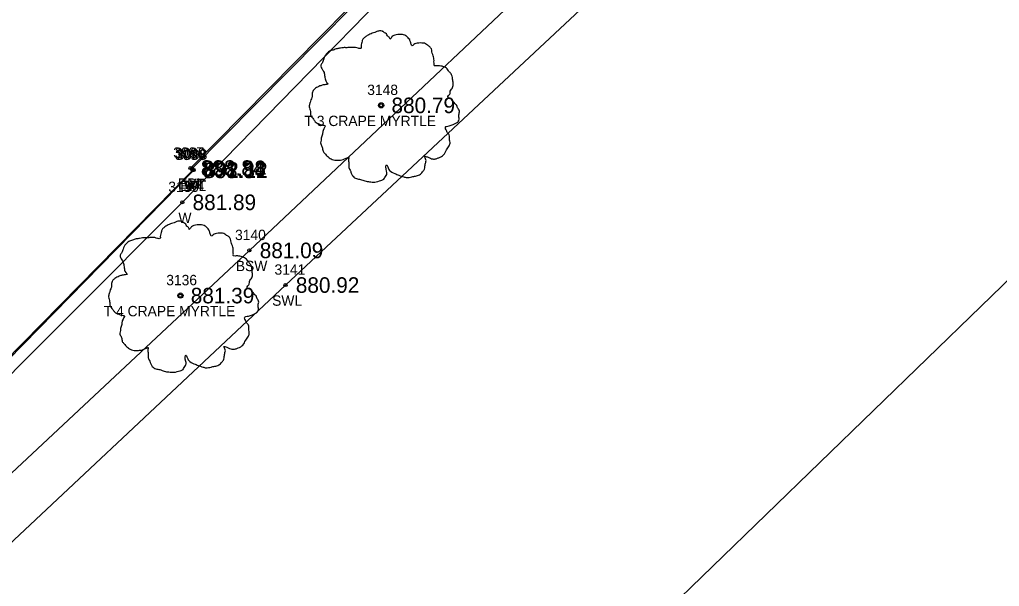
# Model space of a CAD drawing. Extents: x 1622501 to 1626664, y 1117816 to 1121579.
# Drawn here: x 1623634 to 1623728.6, y 1119016.9 to 1119071.7 of the extents above; entities that cross this region are included whole.
import ezdxf

# ---------------------------------------------------------------- set-up
doc = ezdxf.new("R2010")
doc.units = 0
for name, color, linetype in [('RD_EX_BldgApp', 7, 'Continuous'), ('RD_EX_Conc', 7, 'Continuous'), ('RD_EX_Conc_txCode', 7, 'Continuous'), ('RD_EX_Misc', 7, 'Continuous'), ('RD_EX_Misc_txCode', 7, 'Continuous'), ('RD_EX_Road', 7, 'Continuous'), ('RD_EX_Road_txCode', 7, 'Continuous'), ('RD_EX_TX_Conc_ELEV', 7, 'Continuous'), ('RD_EX_TX_Misc_ELEV', 7, 'Continuous'), ('RD_EX_TX_Road_ELEV', 7, 'Continuous'), ('RD_EX_TX_VEG_ELEV', 7, 'Continuous'), ('RD_EX_VEG', 7, 'Continuous'), ('RD_EX_VEG_txCode', 7, 'Continuous'), ('RD_SMD_Locator', 7, 'Continuous')]:
    doc.layers.add(name, color=color, linetype=linetype)

msp = doc.modelspace()

# ---------------------------------------------------------------- linework, layer by layer
at = {"layer": 'RD_EX_BldgApp'}
msp.add_lwpolyline([(1623611.88, 1119041.633), (1623617.165, 1119021.483), (1623649.671, 1119054.028), (1623681.051, 1119086.161), (1623722.347, 1119127.806), (1623757.936, 1119164.001), (1623796.61, 1119203.222), (1623812.892, 1119220.059), (1623805.759, 1119227.093), (1623820.901, 1119266.212)], dxfattribs=at)
at = {"layer": 'RD_EX_Conc'}
for points in [[(1623595.957, 1118993.098), (1623622.153, 1119017.611), (1623656.161, 1119049.385), (1623694.844, 1119085.827), (1623730.881, 1119119.331), (1623767.199, 1119153.546), (1623807.434, 1119191.229), (1623857.127, 1119237.776)], [(1623598.762, 1118988.762), (1623625.502, 1119014.047), (1623659.646, 1119046.042), (1623697.948, 1119081.826), (1623734.479, 1119116.219), (1623770.397, 1119149.723), (1623810.513, 1119187.319), (1623859.029, 1119232.94)]]:
    msp.add_lwpolyline(points, dxfattribs=at)
at = {"layer": 'RD_EX_Misc'}
msp.add_lwpolyline([(1623612.489, 1119041.839), (1623617.784, 1119023.464), (1623650.786, 1119057.144), (1623650.629, 1119057.303), (1623678.345, 1119085.339), (1623703.433, 1119110.78), (1623703.191, 1119111.004), (1623719.28, 1119127.327), (1623719.051, 1119127.54), (1623738.853, 1119148.212), (1623776.594, 1119185.952), (1623789.621, 1119199.191), (1623809.925, 1119220.218), (1623803.282, 1119226.617), (1623818.739, 1119266.256)], dxfattribs=at)
at = {"layer": 'RD_EX_Road'}
for points in [[(1623613.186, 1119042.019), (1623617.82, 1119023.739), (1623650.67, 1119057.113), (1623650.468, 1119057.338), (1623678.183, 1119085.433), (1623703.282, 1119110.828), (1623703.118, 1119110.99), (1623719.085, 1119127.283), (1623718.708, 1119127.648), (1623738.45, 1119148.271), (1623776.492, 1119186.305), (1623774.181, 1119207.708)], [(1623613.186, 1119042.019), (1623611.006, 1119043.814), (1623608.999, 1119042.947), (1623599.734, 1119032.628), (1623594.943, 1119023.41), (1623593.061, 1119016.814), (1623592.292, 1119005.793), (1623594.792, 1118992.799), (1623599.513, 1118985.89), (1623605.793, 1118978.903), (1623613.538, 1118973.355), (1623625.909, 1118968.984), (1623636.836, 1118968.46), (1623647.743, 1118971.195), (1623659.463, 1118979.46), (1623658.889, 1118980.17), (1623658.337, 1118980.438), (1623666.316, 1118985.506), (1623695.703, 1119013.851), (1623731.996, 1119048.998), (1623767.021, 1119082.64), (1623805.037, 1119118.246), (1623840.273, 1119151.616), (1623856.194, 1119167.062)]]:
    msp.add_lwpolyline(points, dxfattribs=at)
at = {"layer": 'RD_EX_VEG'}
for centre, radius in [((1623668.89, 1119063.392), 0.25), ((1623668.877, 1119063.373), 0.0001), ((1623649.496, 1119045.025), 0.25), ((1623649.484, 1119045.006), 0.0001)]:
    msp.add_circle(centre, radius, dxfattribs=at)
for points in [[(1623669.022, 1119070.559), (1623668.722, 1119070.584), (1623668.397, 1119070.484), (1623668.147, 1119070.385), (1623667.922, 1119070.31), (1623667.698, 1119070.21), (1623667.398, 1119070.035), (1623667.173, 1119069.835), (1623667.048, 1119069.585), (1623666.998, 1119069.36), (1623666.948, 1119069.085), (1623666.948, 1119068.91), (1623666.823, 1119068.885), (1623666.673, 1119068.91), (1623666.423, 1119068.985), (1623666.173, 1119068.985), (1623665.923, 1119068.985), (1623665.573, 1119068.96), (1623665.224, 1119068.96), (1623664.949, 1119068.91), (1623664.624, 1119068.86), (1623664.249, 1119068.735), (1623663.899, 1119068.61), (1623663.599, 1119068.36), (1623663.349, 1119067.886), (1623663.224, 1119067.536), (1623663.075, 1119067.286), (1623663.224, 1119066.836), (1623663.399, 1119066.486), (1623663.424, 1119066.286), (1623663.499, 1119065.862), (1623663.599, 1119065.637), (1623663.724, 1119065.437), (1623663.649, 1119065.412), (1623663.274, 1119065.362), (1623662.975, 1119065.262), (1623662.55, 1119065.037), (1623662.325, 1119064.812), (1623662.225, 1119064.487), (1623662.2, 1119064.137), (1623662.1, 1119063.937), (1623662.025, 1119063.662), (1623662, 1119063.587), (1623661.95, 1119063.263), (1623662.05, 1119062.813), (1623662.075, 1119062.463), (1623662.2, 1119062.238), (1623662.35, 1119062.063), (1623662.525, 1119061.813), (1623662.925, 1119061.588), (1623663.249, 1119061.488), (1623663.449, 1119061.463), (1623663.274, 1119060.964), (1623663.224, 1119060.614), (1623663.1, 1119060.214), (1623663.1, 1119060.139), (1623663.05, 1119059.664), (1623663.199, 1119059.339), (1623663.274, 1119058.965), (1623663.449, 1119058.74), (1623663.724, 1119058.44), (1623664.049, 1119058.215), (1623664.549, 1119058.09), (1623664.949, 1119058.115), (1623665.524, 1119058.29), (1623665.773, 1119058.365), (1623665.748, 1119058.19), (1623665.773, 1119057.815), (1623665.773, 1119057.39), (1623665.923, 1119057.065), (1623666.023, 1119056.79), (1623666.173, 1119056.541), (1623666.498, 1119056.316), (1623666.898, 1119056.241), (1623667.323, 1119056.091), (1623667.773, 1119056.016), (1623668.272, 1119055.991), (1623668.872, 1119056.141), (1623669.147, 1119056.266), (1623669.247, 1119056.441), (1623669.447, 1119056.815), (1623669.397, 1119057.04), (1623669.422, 1119057.64), (1623669.522, 1119057.465), (1623669.697, 1119057.115), (1623670.196, 1119056.815), (1623670.596, 1119056.641), (1623671.071, 1119056.491), (1623671.371, 1119056.416), (1623671.846, 1119056.491), (1623672.221, 1119056.566), (1623672.595, 1119056.691), (1623672.895, 1119056.965), (1623673.07, 1119057.24), (1623673.12, 1119057.515), (1623673.195, 1119057.89), (1623673.245, 1119058.065)], [(1623673.245, 1119058.065), (1623673.17, 1119058.24), (1623673.12, 1119058.49), (1623673.195, 1119058.465), (1623673.37, 1119058.415), (1623673.645, 1119058.29), (1623673.87, 1119058.215), (1623674.195, 1119058.24), (1623674.47, 1119058.34), (1623674.919, 1119058.615), (1623675.194, 1119059.089), (1623675.469, 1119059.489), (1623675.544, 1119059.814), (1623675.494, 1119060.039), (1623675.469, 1119060.539), (1623675.269, 1119060.789), (1623675.219, 1119060.914), (1623675.119, 1119061.313), (1623675.194, 1119061.363), (1623675.469, 1119061.413), (1623675.844, 1119061.538), (1623676.119, 1119061.663), (1623676.344, 1119061.838), (1623676.419, 1119062.063), (1623676.394, 1119062.463), (1623676.444, 1119062.863), (1623676.369, 1119063.013), (1623676.269, 1119063.163), (1623676.194, 1119063.363), (1623676.044, 1119063.512), (1623675.944, 1119063.662), (1623675.844, 1119063.762), (1623675.719, 1119063.912), (1623675.544, 1119064.037), (1623675.394, 1119064.087), (1623675.344, 1119064.237), (1623675.494, 1119064.437), (1623675.544, 1119064.537), (1623675.569, 1119064.762), (1623675.794, 1119065.112), (1623675.844, 1119065.512), (1623675.794, 1119065.936), (1623675.744, 1119066.211), (1623675.594, 1119066.486), (1623675.394, 1119066.736), (1623675.269, 1119066.911), (1623675.094, 1119067.036), (1623674.769, 1119067.161), (1623674.52, 1119067.211), (1623674.17, 1119067.211), (1623673.97, 1119067.261), (1623673.995, 1119067.311), (1623673.995, 1119067.461), (1623673.995, 1119067.736), (1623673.92, 1119068.185), (1623673.77, 1119068.685), (1623673.77, 1119068.71), (1623673.67, 1119068.96), (1623673.445, 1119069.16), (1623673.27, 1119069.26), (1623673.07, 1119069.385), (1623672.82, 1119069.41), (1623672.52, 1119069.41), (1623672.246, 1119069.36), (1623672.046, 1119069.26), (1623671.871, 1119069.135), (1623671.796, 1119069.285), (1623671.696, 1119069.585), (1623671.646, 1119069.735), (1623671.496, 1119069.91), (1623671.271, 1119070.11), (1623670.821, 1119070.235), (1623670.196, 1119070.16), (1623669.897, 1119069.96), (1623669.747, 1119069.785), (1623669.697, 1119069.91), (1623669.497, 1119070.11), (1623669.397, 1119070.285), (1623669.222, 1119070.41), (1623669.072, 1119070.509), (1623668.972, 1119070.559)], [(1623649.628, 1119052.192), (1623649.328, 1119052.217), (1623649.004, 1119052.117), (1623648.754, 1119052.017), (1623648.529, 1119051.942), (1623648.304, 1119051.842), (1623648.004, 1119051.667), (1623647.779, 1119051.468), (1623647.654, 1119051.218), (1623647.604, 1119050.993), (1623647.554, 1119050.718), (1623647.554, 1119050.543), (1623647.429, 1119050.518), (1623647.279, 1119050.543), (1623647.029, 1119050.618), (1623646.779, 1119050.618), (1623646.53, 1119050.618), (1623646.18, 1119050.593), (1623645.83, 1119050.593), (1623645.555, 1119050.543), (1623645.23, 1119050.493), (1623644.855, 1119050.368), (1623644.505, 1119050.243), (1623644.206, 1119049.993), (1623643.956, 1119049.518), (1623643.831, 1119049.169), (1623643.681, 1119048.919), (1623643.831, 1119048.469), (1623644.006, 1119048.119), (1623644.031, 1119047.919), (1623644.106, 1119047.494), (1623644.206, 1119047.269), (1623644.331, 1119047.069), (1623644.256, 1119047.045), (1623643.881, 1119046.995), (1623643.581, 1119046.895), (1623643.156, 1119046.67), (1623642.931, 1119046.445), (1623642.831, 1119046.12), (1623642.806, 1119045.77), (1623642.706, 1119045.57), (1623642.631, 1119045.295), (1623642.606, 1119045.22), (1623642.556, 1119044.895), (1623642.656, 1119044.446), (1623642.681, 1119044.096), (1623642.806, 1119043.871), (1623642.956, 1119043.696), (1623643.131, 1119043.446), (1623643.531, 1119043.221), (1623643.856, 1119043.121), (1623644.056, 1119043.096), (1623643.881, 1119042.596), (1623643.831, 1119042.247), (1623643.706, 1119041.847), (1623643.706, 1119041.772), (1623643.656, 1119041.297), (1623643.806, 1119040.972), (1623643.881, 1119040.597), (1623644.056, 1119040.372), (1623644.331, 1119040.073), (1623644.655, 1119039.848), (1623645.155, 1119039.723), (1623645.555, 1119039.748), (1623646.13, 1119039.923), (1623646.38, 1119039.998), (1623646.355, 1119039.823), (1623646.38, 1119039.448), (1623646.38, 1119039.023), (1623646.53, 1119038.698), (1623646.63, 1119038.423), (1623646.779, 1119038.173), (1623647.104, 1119037.948), (1623647.504, 1119037.873), (1623647.929, 1119037.724), (1623648.379, 1119037.649), (1623648.879, 1119037.624), (1623649.478, 1119037.773), (1623649.753, 1119037.898), (1623649.853, 1119038.073), (1623650.053, 1119038.448), (1623650.003, 1119038.673), (1623650.028, 1119039.273), (1623650.128, 1119039.098), (1623650.303, 1119038.748), (1623650.803, 1119038.448), (1623651.203, 1119038.273), (1623651.677, 1119038.123), (1623651.977, 1119038.048), (1623652.452, 1119038.123), (1623652.827, 1119038.198), (1623653.202, 1119038.323), (1623653.502, 1119038.598), (1623653.676, 1119038.873), (1623653.726, 1119039.148), (1623653.801, 1119039.523), (1623653.851, 1119039.698)], [(1623653.851, 1119039.698), (1623653.776, 1119039.873), (1623653.726, 1119040.123), (1623653.801, 1119040.097), (1623653.976, 1119040.047), (1623654.251, 1119039.923), (1623654.476, 1119039.848), (1623654.801, 1119039.873), (1623655.076, 1119039.973), (1623655.526, 1119040.248), (1623655.801, 1119040.722), (1623656.075, 1119041.122), (1623656.15, 1119041.447), (1623656.1, 1119041.672), (1623656.075, 1119042.172), (1623655.875, 1119042.421), (1623655.825, 1119042.546), (1623655.726, 1119042.946), (1623655.801, 1119042.996), (1623656.075, 1119043.046), (1623656.45, 1119043.171), (1623656.725, 1119043.296), (1623656.95, 1119043.471), (1623657.025, 1119043.696), (1623657, 1119044.096), (1623657.05, 1119044.496), (1623656.975, 1119044.646), (1623656.875, 1119044.795), (1623656.8, 1119044.995), (1623656.65, 1119045.145), (1623656.55, 1119045.295), (1623656.45, 1119045.395), (1623656.325, 1119045.545), (1623656.15, 1119045.67), (1623656, 1119045.72), (1623655.95, 1119045.87), (1623656.1, 1119046.07), (1623656.15, 1119046.17), (1623656.175, 1119046.395), (1623656.4, 1119046.745), (1623656.45, 1119047.144), (1623656.4, 1119047.569), (1623656.35, 1119047.844), (1623656.2, 1119048.119), (1623656, 1119048.369), (1623655.875, 1119048.544), (1623655.701, 1119048.669), (1623655.376, 1119048.794), (1623655.126, 1119048.844), (1623654.776, 1119048.844), (1623654.576, 1119048.894), (1623654.601, 1119048.944), (1623654.601, 1119049.094), (1623654.601, 1119049.369), (1623654.526, 1119049.818), (1623654.376, 1119050.318), (1623654.376, 1119050.343), (1623654.276, 1119050.593), (1623654.051, 1119050.793), (1623653.876, 1119050.893), (1623653.676, 1119051.018), (1623653.427, 1119051.043), (1623653.127, 1119051.043), (1623652.852, 1119050.993), (1623652.652, 1119050.893), (1623652.477, 1119050.768), (1623652.402, 1119050.918), (1623652.302, 1119051.218), (1623652.252, 1119051.368), (1623652.102, 1119051.542), (1623651.877, 1119051.742), (1623651.427, 1119051.867), (1623650.803, 1119051.792), (1623650.503, 1119051.593), (1623650.353, 1119051.418), (1623650.303, 1119051.542), (1623650.103, 1119051.742), (1623650.003, 1119051.917), (1623649.828, 1119052.042), (1623649.678, 1119052.142), (1623649.578, 1119052.192)]]:
    msp.add_spline(points, degree=3, dxfattribs=at)
at = {"layer": 'RD_SMD_Locator'}
for centre in [(1623668.89, 1119063.392), (1623650.468, 1119057.338), (1623650.629, 1119057.303), (1623650.67, 1119057.113), (1623650.786, 1119057.144), (1623649.671, 1119054.028), (1623656.161, 1119049.385), (1623659.646, 1119046.042), (1623649.496, 1119045.025)]:
    msp.add_circle(centre, 0.15, dxfattribs=at)

# ---------------------------------------------------------------- texts
at = {"layer": 'RD_EX_Conc_txCode'}
for s, p in [('3140', (1623654.775, 1119050.385)), ('BSW', (1623654.846, 1119047.385)), ('3141', (1623658.583, 1119047.042)), ('SWL', (1623658.355, 1119044.042))]:
    msp.add_text(s, height=1, dxfattribs=at).set_placement(p)
at = {"layer": 'RD_EX_Misc_txCode'}
for s, p in [('3099', (1623648.96, 1119058.303)), ('3098', (1623649.117, 1119058.144)), ('3139', (1623648.325, 1119055.028)), ('WT', (1623649.771, 1119055.303)), ('WT', (1623649.928, 1119055.144)), ('W', (1623649.301, 1119052.028))]:
    msp.add_text(s, height=1, dxfattribs=at).set_placement(p)
at = {"layer": 'RD_EX_Road_txCode'}
for s, p in [('3097', (1623648.798, 1119058.338)), ('3096', (1623648.977, 1119058.113)), ('EPL', (1623649.263, 1119055.338)), ('EPL', (1623649.465, 1119055.113))]:
    msp.add_text(s, height=1, dxfattribs=at).set_placement(p)
at = {"layer": 'RD_EX_TX_Conc_ELEV'}
for s, p in [('881.09', (1623657.161, 1119048.635)), ('880.92', (1623660.646, 1119045.292))]:
    msp.add_text(s, height=1.5, dxfattribs=at).set_placement(p)
at = {"layer": 'RD_EX_TX_Misc_ELEV'}
for s, p in [('891.98', (1623651.629, 1119056.553)), ('892.12', (1623651.786, 1119056.394)), ('881.89', (1623650.671, 1119053.278))]:
    msp.add_text(s, height=1.5, dxfattribs=at).set_placement(p)
at = {"layer": 'RD_EX_TX_Road_ELEV'}
for p in [(1623651.468, 1119056.588), (1623651.67, 1119056.363)]:
    msp.add_text('888.84', height=1.5, dxfattribs=at).set_placement(p)
at = {"layer": 'RD_EX_TX_VEG_ELEV'}
for s, p in [('880.79', (1623669.89, 1119062.642)), ('881.39', (1623650.496, 1119044.275))]:
    msp.add_text(s, height=1.5, dxfattribs=at).set_placement(p)
at = {"layer": 'RD_EX_VEG_txCode'}
for s, p in [('3148', (1623667.544, 1119064.392)), ('T 3 CRAPE MYRTLE', (1623661.484, 1119061.392)), ('3136', (1623648.126, 1119046.025)), ('T 4 CRAPE MYRTLE', (1623642.091, 1119043.025))]:
    msp.add_text(s, height=1, dxfattribs=at).set_placement(p)

doc.saveas('drawing.dxf')
